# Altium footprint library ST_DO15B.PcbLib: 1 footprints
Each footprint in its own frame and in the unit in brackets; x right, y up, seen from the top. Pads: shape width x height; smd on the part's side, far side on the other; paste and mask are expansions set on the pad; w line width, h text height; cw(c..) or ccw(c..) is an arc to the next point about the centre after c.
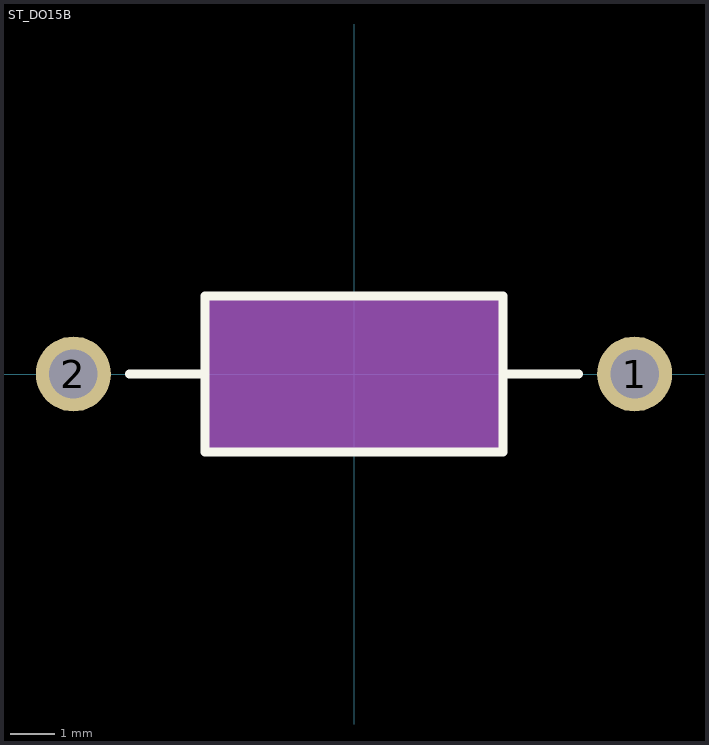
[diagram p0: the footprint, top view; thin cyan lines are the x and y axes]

## ST_DO15B [mm]
pads (2):
  round 1.7 hole 1.1: 1(6.35,0) 2(-6.35,0)
Top Overlay:
  lines w0.2: -5.08,0 -3.434,0 ; 3.375,0 5.08,0 ; -3.375,-1.765 3.375,-1.765 3.375,1.765 -3.375,1.765 -3.375,-1.765
3D Top (Mech13):
  rectangle: -3.375,-1.765 3.375,1.765
3D body: height 3.53, standoff 0, extent -2.921,1.016 -2.921,1.016
3D body "DO15.step": height 3.52, standoff 0.01, extent -3.375,-1.76 3.375,1.76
